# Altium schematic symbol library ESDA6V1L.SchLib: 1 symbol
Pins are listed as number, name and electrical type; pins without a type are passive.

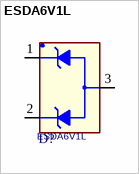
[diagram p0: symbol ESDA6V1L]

## ESDA6V1L
designator D?
footprint ST_SOT23-3L
pins: 1 K1, 2 K2, 3 A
